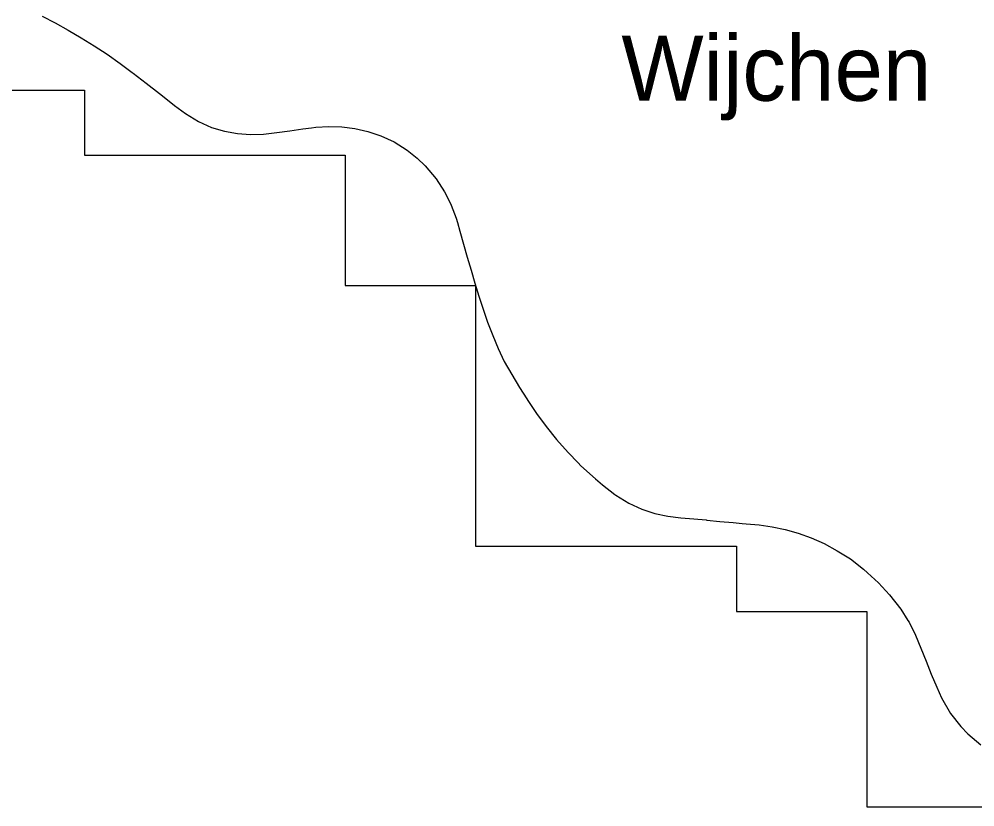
# Model space of a CAD drawing. Extents: x 113371 to 291721, y 393993 to 520143.
# Drawn here: x 169499 to 176829, y 420500 to 426544 of the extents above; entities that cross this region are included whole.
import ezdxf

# ---------------------------------------------------------------- set-up
doc = ezdxf.new("R2010")
doc.units = 0
for name, color, linetype in [('Boudingbox', 7, 'Continuous'), ('Default', 7, 'Continuous'), ('plaatsnamen', 7, 'Continuous')]:
    doc.layers.add(name, color=color, linetype=linetype)

msp = doc.modelspace()

# ---------------------------------------------------------------- linework, layer by layer
at = {"layer": 'Boudingbox'}
for p, q in [((169000, 426000), (170000, 426000)), ((170000, 426000), (170000, 425500)), ((170000, 425500), (172000, 425500)), ((172000, 425500), (172000, 424500)), ((172000, 424500), (173000, 424500)), ((173000, 424500), (173000, 422500)), ((173000, 422500), (175000, 422500)), ((175000, 422500), (175000, 422000)), ((175000, 422000), (176000, 422000)), ((176000, 422000), (176000, 420500)), ((176000, 420500), (180000, 420500))]:
    msp.add_line(p, q, dxfattribs=at)
at = {"layer": 'Default'}
for points in [[(169674.285625, 426565.7525), (169774.285625, 426514.7525), (169874.285625, 426458.7525), (169974.285625, 426400.7525), (170074.285625, 426339.7525), (170174.285625, 426274.7525), (170274.285625, 426202.7525), (170366.885625, 426134.2325), (170374.285625, 426128.7525), (170474.285625, 426051.7525), (170574.285625, 425972.7525), (170674.285625, 425894.7525), (170691.605625, 425881.7725), (170774.285625, 425819.7525), (170874.285625, 425758.7525), (170974.285625, 425711.7525), (171074.285625, 425683.7525), (171174.285625, 425665.7525), (171274.375625, 425658.3325), (171374.285625, 425661.7525), (171474.285625, 425673.7525), (171574.285625, 425687.7525), (171674.285625, 425701.7525), (171741.995625, 425710.5625), (171774.285625, 425714.7525), (171874.285625, 425719.7525), (171974.285625, 425718.7525), (172074.285625, 425705.7525), (172174.285625, 425681.7525), (172274.285625, 425648.7525), (172374.285625, 425601.7525), (172474.285625, 425539.7525), (172552.285625, 425477.7525)], [(172552.285625, 425477.7525), (172614.285625, 425417.7525), (172696.285625, 425317.7525), (172762.285625, 425217.7525), (172773.335625, 425195.6725), (172812.285625, 425117.7525), (172850.285625, 425017.7525), (172860.125625, 424983.8325), (172879.285625, 424917.7525), (172908.285625, 424817.7525), (172935.285625, 424717.7525), (172966.285625, 424617.7525), (172994.285625, 424517.7525), (173025.285625, 424417.7525), (173044.335625, 424358.2425), (173057.285625, 424317.7525), (173092.285625, 424217.7525), (173131.285625, 424117.7525), (173172.285625, 424017.7525), (173220.285625, 423917.7525), (173277.285625, 423817.7525), (173337.285625, 423717.7525), (173364.305625, 423674.8725), (173392.295625, 423630.4525), (173400.285625, 423617.7525), (173466.285625, 423517.7525), (173540.285625, 423417.7525), (173619.285625, 423317.7525), (173709.285625, 423217.7525), (173786.005625, 423139.4825), (173807.285625, 423117.7525), (173919.285625, 423017.7525), (173974.285625, 422969.7525), (174066.915625, 422897.5025), (174074.285625, 422891.7525), (174174.285625, 422830.7525), (174274.285625, 422784.7525), (174374.285625, 422751.7525)], [(174374.285625, 422751.7525), (174474.285625, 422729.7525), (174574.285625, 422716.7525), (174674.285625, 422708.7525), (174767.475625, 422701.3025), (174774.285625, 422700.7525), (174874.285625, 422690.7525), (174974.285625, 422681.7525), (175043.635625, 422674.8225), (175074.285625, 422671.7525), (175174.285625, 422662.7525), (175274.285625, 422648.7525), (175374.285625, 422627.7525), (175474.285625, 422599.7525), (175574.285625, 422564.7525), (175674.285625, 422519.7525), (175774.285625, 422465.7525), (175874.285625, 422402.7525), (175974.285625, 422324.7525), (176005.365625, 422296.0925), (176090.285625, 422217.7525), (176174.285625, 422127.7525), (176260.285625, 422017.7525), (176315.955625, 421930.7825), (176324.285625, 421917.7525), (176374.285625, 421817.7525), (176414.285625, 421717.7525), (176455.285625, 421617.7525), (176495.285625, 421517.7525), (176536.285625, 421417.7525), (176554.985625, 421377.9025), (176574.285625, 421336.7525), (176643.285625, 421217.7525), (176720.285625, 421117.7525), (176774.285625, 421059.7525), (176874.285625, 420976.7525)]]:
    msp.add_lwpolyline(points, dxfattribs=at)

# ---------------------------------------------------------------- texts
at = {"layer": 'plaatsnamen'}
msp.add_text('Wijchen', height=500, dxfattribs=at).set_placement((174118.050291, 425917.407294))

doc.saveas('drawing.dxf')
